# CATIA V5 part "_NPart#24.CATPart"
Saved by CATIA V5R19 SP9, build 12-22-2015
Part number: NES-350(внешн_мод)_1
Definition: design
Nomenclature: NES-350(внешн_мод)
Source: Unknown
Bounding box of the stored display mesh (mm): x -215 to 12, y -115 to 0, z 0 to 50
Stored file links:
  Z:\charly_robot\_NPart#24.CATPart
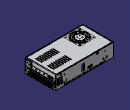
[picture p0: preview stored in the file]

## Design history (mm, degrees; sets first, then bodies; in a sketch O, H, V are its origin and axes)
AxisSystem1: origin (0, 0, 0), X (1, 0, 0), Y (0, 1, 0), Z (0, 0, 1)
Body1 "Тело_0:59" (main body)
  Solid1: solid without history
Body2 "Тело_0:58"
  Solid2: solid without history
Body3 "Тело_0:57"
  Solid3: solid without history
Body4 "Тело_0:56"
  Solid4: solid without history
Body5 "Тело_0:55"
  Solid5: solid without history
Body6 "Тело_0:54"
  Solid6: solid without history
Body7 "Тело_0:53"
  Solid7: solid without history
Body8 "Тело_0:52"
  Solid8: solid without history
Body9 "Тело_0:51"
  Solid9: solid without history
Body10 "Тело_0:50"
  Solid10: solid without history
Body11 "Тело_0:49"
  Solid11: solid without history
Body12 "Тело_0:48"
  Solid12: solid without history
Body13 "Тело_0:47"
  Solid13: solid without history
Body14 "Тело_0:46"
  Solid14: solid without history
Body15 "Тело_0:45"
  Solid15: solid without history
Body16 "Тело_0:44"
  Solid16: solid without history
Body17 "Тело_0:43"
  Solid17: solid without history
Body18 "Тело_0:42"
  Solid18: solid without history
Body19 "Тело_0:41"
  Solid19: solid without history
Body20 "Тело_0:40"
  Solid20: solid without history
Body21 "Тело_0:39"
  Solid21: solid without history
Body22 "Тело_0:38"
  Solid22: solid without history
Body23 "Тело_0:37"
  Solid23: solid without history
Body24 "Тело_0:36"
  Solid24: solid without history
Body25 "Тело_0:35"
  Solid25: solid without history
Body26 "Тело_0:34"
  Solid26: solid without history
Body27 "Тело_0:33"
  Solid27: solid without history
Body28 "Тело_0:32"
  Solid28: solid without history
Body29 "Тело_0:31"
  Solid29: solid without history
Body30 "Тело_0:30"
  Solid30: solid without history
Body31 "Тело_0:29"
  Solid31: solid without history
Body32 "Тело_0:28"
  Solid32: solid without history
Body33 "Тело_0:27"
  Solid33: solid without history
Body34 "Тело_0:26"
  Solid34: solid without history
Body35 "Тело_0:25"
  Solid35: solid without history
Body36 "Тело_0:24"
  Solid36: solid without history
Body37 "Тело_0:23"
  Solid37: solid without history
Body38 "Тело_0:22"
  Solid38: solid without history
Body39 "Тело_0:21"
  Solid39: solid without history
Body40 "Тело_0:20"
  Solid40: solid without history
Body41 "Тело_0:19"
  Solid41: solid without history
Body42 "Тело_0:18"
  Solid42: solid without history
Body43 "Тело_0:17"
  Solid43: solid without history
Body44 "Тело_0:16"
  Solid44: solid without history
Body45 "Тело_0:15"
  Solid45: solid without history
Body46 "Тело_0:14"
  Solid46: solid without history
Body47 "Тело_0:13"
  Solid47: solid without history
Body48 "Тело_0:12"
  Solid48: solid without history
Body49 "Тело_0:11"
  Solid49: solid without history
Body50 "Тело_0:10"
  Solid50: solid without history
Body51 "Тело_0:9"
  Solid51: solid without history
Body52 "Тело_0:8"
  Solid52: solid without history
Body53 "Тело_0:7"
  Solid53: solid without history
Body54 "Тело_0:6"
  Solid54: solid without history
Body55 "Тело_0:5"
  Solid55: solid without history
Body56 "Тело_0:4"
  Solid56: solid without history
Body57 "Тело_0:3"
  Solid57: solid without history
Body58 "Тело_0:2"
  Solid58: solid without history
Body59 "Тело_0:1"
  Solid59: solid without history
